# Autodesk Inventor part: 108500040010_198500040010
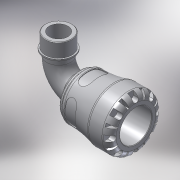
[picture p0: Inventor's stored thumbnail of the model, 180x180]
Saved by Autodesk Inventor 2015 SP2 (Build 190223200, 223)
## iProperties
Created: 2016-12
Part Number: 108500040010_198500040010
Material: PVC-Piping
Description: PLASSON 90° ELBOW WITH THREADED MALE OFFTAKE 40X1" SERIES 1
Document SubType Name: Modeling
Designer: KIM
Mass: 264.092 g
Surface Area: 450.075 cm^2
Volume: 188.637 cm^3
Density: 1.4 g/cm^3
Appearance: Smooth - White
Author: KIM
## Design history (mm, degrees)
derived "1085.ipt"
feature "Solid1::1085.ipt"
tag "TaggingFeature1"
body "Solid1"
other parameters: "d1" = 29.82, "d8" = 59.5, "d13" = 8, "d14" = 8, "d15" = 0, "d17" = 360 deg, "d19" = 8 deg, "d20" = 0.8, "d21" = 0.8, "d22" = 8 deg, "d24" = 0, "d26" = 360 deg, "d33" = 7, "d43" = 54.6, "d51" = 0.7, "d54" = 14, "d55" = 8.8, "d57" = 15.68, "d58" = 0, "d74" = 0, "d78" = 71, "d82" = 0.8, "d115" = 360 deg, "d207" = 90 deg, "d228" = 11.9, "d247" = 1.4, "d248" = 4.26, "d268" = 32.725, "d269" = 4.26, "d270" = 107, "d276" = 33.249, "d277" = 19, "d278" = 36.5739, "d279" = 57, "d280" = 20.9, "d281" = 4.98735, "d283" = 29.9241, "d286" = 0, "d287" = 0, "d288" = 23.2743, "d290" = 12.33795, "d292" = 30 deg, "l_" = 71, "A_" = 107, "A_1" = 57, "l_2" = 19, "R_" = 33.249, "d9" = 10, "d289" = 23.2743
